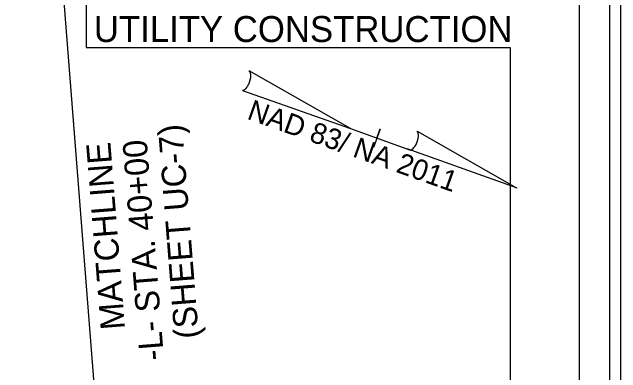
# Model space of a CAD drawing. Extents: x 0 to 7954, y -383 to 1504.
# Drawn here: x 2.4159 to 2.8333, y 1.2767 to 1.5238 of the extents above; entities that cross this region are included whole.
import ezdxf

# ---------------------------------------------------------------- set-up
doc = ezdxf.new("R2010")
doc.units = 0
for name, color, linetype in [('Scratch_Level_3', 7, 'Continuous'), ('UC Notes and Details Sheet 34 CELL', 7, 'Continuous'), ('UC Plan Profile Sheet 34 CELL', 7, 'Continuous')]:
    doc.layers.add(name, color=color, linetype=linetype)

msp = doc.modelspace()

# ---------------------------------------------------------------- linework, layer by layer
at = {"layer": 'Scratch_Level_3'}
msp.add_lwpolyline([(0.36636, 0.9085), (0.36636, 1.69148), (2.46666, 1.69148), (2.46666, 1.49966), (2.75747, 1.49966), (2.75747, 0.9085)], close=True, dxfattribs=at)
at = {"layer": 'UC Notes and Details Sheet 34 CELL'}
for p, q in [((2.64785, 1.44402), (2.57833, 1.48355)), ((2.57395, 1.47025), (2.64785, 1.44402)), ((2.64785, 1.44402), (2.68898, 1.42937)), ((2.66827, 1.44374), (2.6638, 1.43118)), ((2.66631, 1.43824), (2.6683, 1.44382)), ((2.6683, 1.44382), (2.66833, 1.44389)), ((2.69368, 1.4423), (2.76186, 1.40351)), ((2.76184, 1.40343), (2.68679, 1.43015)), ((2.68679, 1.43015), (2.68891, 1.4294)), ((2.76184, 1.40343), (2.76181, 1.40335)), ((2.76184, 1.40343), (2.76181, 1.40335))]:
    msp.add_line(p, q, dxfattribs=at)
for centre, start_param, end_param in [((2.5757, 1.47699), 0.201328, 3.141593), ((2.69059, 1.43608), 0.216388, 2.908219)]:
    msp.add_ellipse(centre, major_axis=(-0.00241, -0.00662), ratio=0.461098, start_param=start_param, end_param=end_param, dxfattribs=at)
at = {"layer": 'UC Plan Profile Sheet 34 CELL'}
msp.add_line((2.49092, 1.03177), (2.4455, 1.60759), dxfattribs=at)
for points in [[(0.02749, 0.00833), (2.83333, 0.00833), (2.83333, 1.83333), (0.02749, 1.83333)], [(0.04916, 0.04166), (2.82583, 0.04166), (2.82583, 1.8), (0.04916, 1.8)], [(2.80499, 1.79583), (0.30499, 1.79583), (0.30499, 0.04583), (2.80499, 0.04583)]]:
    msp.add_lwpolyline(points, close=True, dxfattribs=at)

# ---------------------------------------------------------------- texts
at = {"layer": 'UC Notes and Details Sheet 34 CELL'}
msp.add_text('NAD 83/ NA 2011', height=0.0141667, rotation=340.3976, dxfattribs=at).set_placement((2.57628, 1.4509))
at = {"layer": 'UC Plan Profile Sheet 34 CELL'}
msp.add_text('UTILITY CONSTRUCTION', height=0.0178124, dxfattribs=at).set_placement((2.4719, 1.50337))
for s, height, p in [('(SHEET UC-7)', 0.0166667, (2.54395, 1.30072)), ('MATCHLINE ', 0.016667, (2.49331, 1.30686)), ('-L- STA. 40+00', 0.0166667, (2.52006, 1.28571))]:
    msp.add_text(s, height=height, rotation=94.5096, dxfattribs=at).set_placement(p)

doc.saveas('drawing.dxf')
